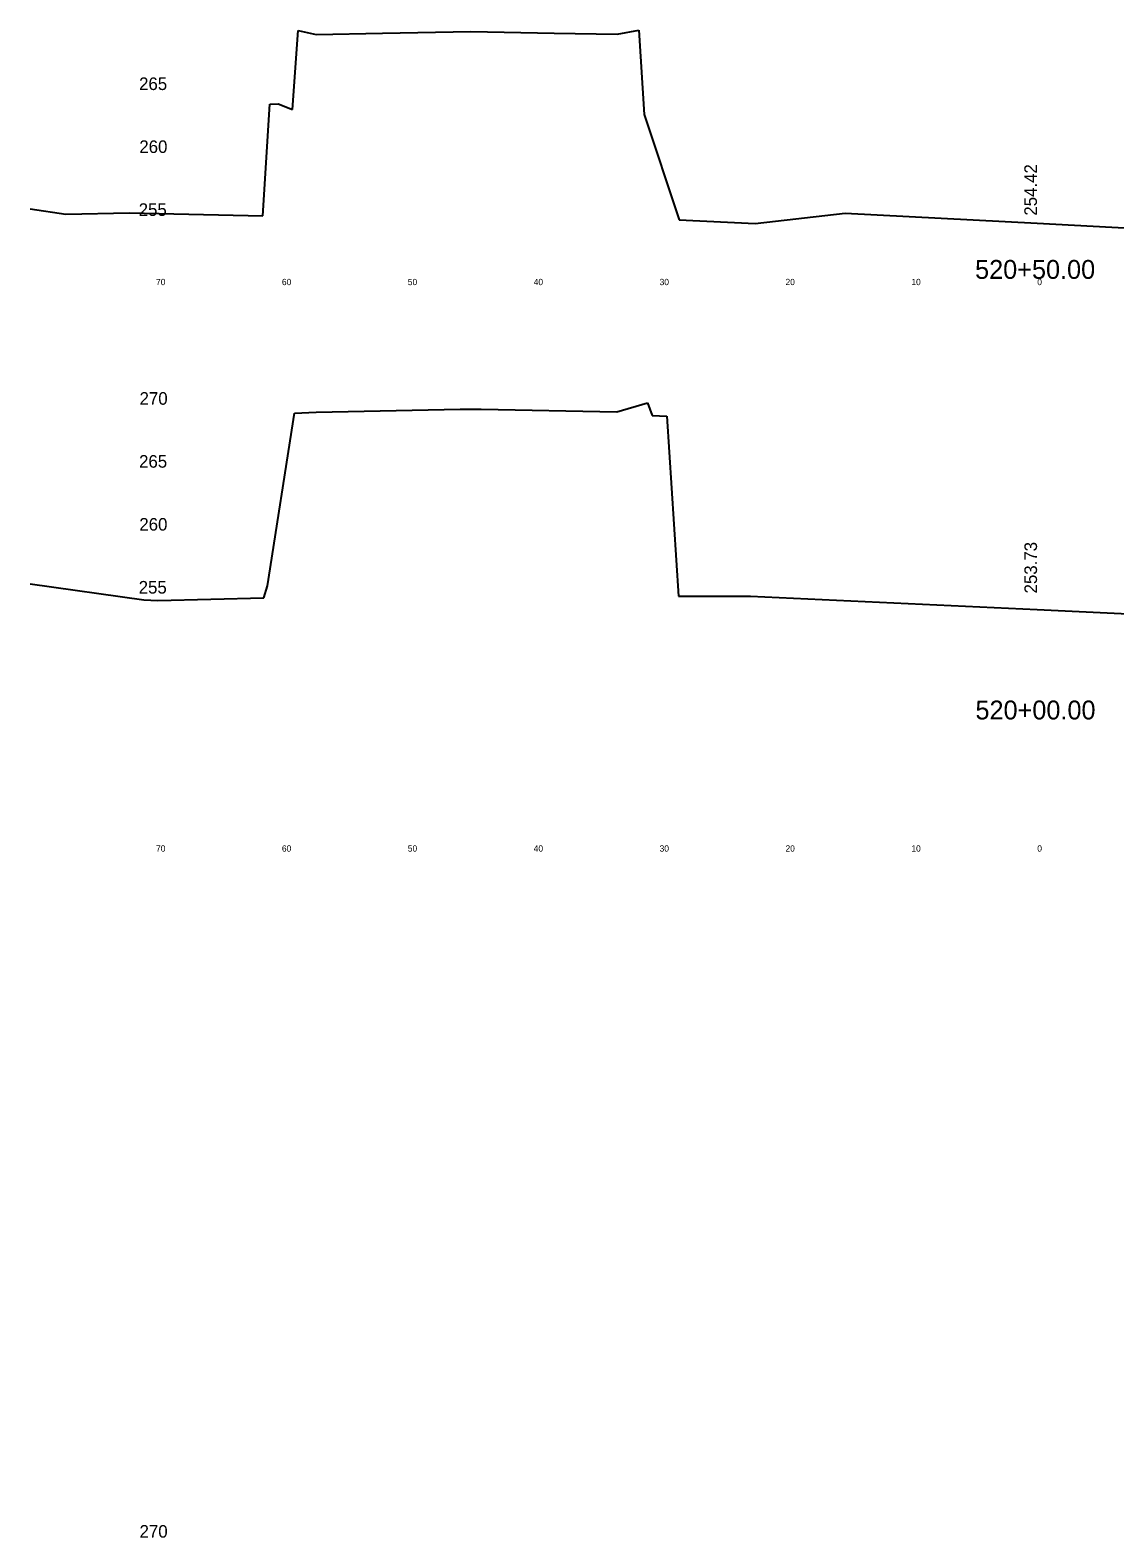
# Model space of a CAD drawing. Extents: x 1000 to 1162, y 999 to 8520.
# Drawn here: x 1000 to 1086.2, y 3820 to 3939.8 of the extents above; entities that cross this region are included whole.
import ezdxf

# ---------------------------------------------------------------- set-up
doc = ezdxf.new("R2010")
doc.units = 0
for name, color, linetype in [('Level 10', 7, 'Continuous'), ('Level 11', 7, 'Continuous'), ('Level 3', 7, 'Continuous'), ('Level 56', 7, 'Continuous'), ('Level 60', 7, 'Continuous')]:
    doc.layers.add(name, color=color, linetype=linetype)

msp = doc.modelspace()

# ---------------------------------------------------------------- linework, layer by layer
at = {"layer": 'Level 60'}
for p, q in [((1020.85, 3933.45), (1021.28, 3939.74)), ((1021.28, 3939.74), (1022.72, 3939.4)), ((1022.72, 3939.4), (1027.98, 3939.51)), ((1027.98, 3939.51), (1035.01, 3939.64)), ((1035.01, 3939.64), (1041.63, 3939.52)), ((1041.63, 3939.52), (1046.64, 3939.44)), ((1046.64, 3939.44), (1048.34, 3939.76)), ((1048.34, 3939.76), (1048.77, 3933.06)), ((1018.49, 3925.01), (1019.05, 3933.89)), ((1019.05, 3933.89), (1019.71, 3933.91)), ((1019.71, 3933.91), (1020.85, 3933.45)), ((1048.77, 3933.06), (1051.55, 3924.7)), ((1000, 3925.55), (1002.84, 3925.15)), ((1002.84, 3925.15), (1007.89, 3925.25)), ((1007.89, 3925.25), (1018.49, 3925.01)), ((1057.6, 3924.39), (1064.73, 3925.23)), ((1064.73, 3925.23), (1080, 3924.42)), ((1051.55, 3924.7), (1057.6, 3924.39)), ((1080, 3924.42), (1107.94, 3922.93)), ((1021.01, 3909.33), (1022.71, 3909.42)), ((1022.71, 3909.42), (1034.17, 3909.64)), ((1034.17, 3909.64), (1035.04, 3909.66)), ((1035.04, 3909.66), (1035.83, 3909.64)), ((1035.83, 3909.64), (1046.61, 3909.44)), ((1046.61, 3909.44), (1049.05, 3910.16)), ((1049.05, 3910.16), (1049.42, 3909.15)), ((1018.85, 3895.61), (1021.01, 3909.33)), ((1049.42, 3909.15), (1050.57, 3909.1)), ((1050.57, 3909.1), (1051.5, 3894.8)), ((1000, 3895.76), (1009.02, 3894.49)), ((1018.56, 3894.65), (1018.85, 3895.61)), ((1009.02, 3894.49), (1010.14, 3894.45)), ((1010.14, 3894.45), (1018.56, 3894.65)), ((1051.5, 3894.8), (1057.21, 3894.79)), ((1057.21, 3894.79), (1080, 3893.73)), ((1080, 3893.73), (1125.1, 3891.63))]:
    msp.add_line(p, q, dxfattribs=at)

# ---------------------------------------------------------------- texts
at = {"layer": 'Level 10'}
for s, p in [('254.42', (1079.97, 3925.02)), ('253.73', (1079.98, 3895.01))]:
    msp.add_text(s, height=1, rotation=90, dxfattribs=at).set_placement(p)
at = {"layer": 'Level 11'}
for s, p in [(' 265', (1008.28, 3935)), (' 260', (1008.3, 3930)), (' 255', (1008.25, 3925)), (' 270', (1008.32, 3910)), (' 265', (1008.28, 3905)), (' 260', (1008.3, 3900)), (' 255', (1008.25, 3895)), (' 270', (1008.32, 3820))]:
    msp.add_text(s, height=1, dxfattribs=at).set_placement(p)
at = {"layer": 'Level 3'}
for s, p in [('520+50.00', (1075.06, 3920)), ('520+00.00', (1075.09, 3885))]:
    msp.add_text(s, height=1.5, dxfattribs=at).set_placement(p)
at = {"layer": 'Level 56'}
for s, p in [('70', (1010, 3919.5)), ('60', (1020, 3919.5)), ('50', (1030, 3919.5)), ('40', (1040, 3919.5)), ('30', (1050, 3919.5)), ('20', (1060, 3919.5)), ('10', (1070, 3919.5)), ('0', (1080, 3919.5)), ('70', (1010, 3874.5)), ('60', (1020, 3874.5)), ('50', (1030, 3874.5)), ('40', (1040, 3874.5)), ('30', (1050, 3874.5)), ('20', (1060, 3874.5)), ('10', (1070, 3874.5)), ('0', (1080, 3874.5))]:
    msp.add_text(s, height=0.5, dxfattribs=at).set_placement(p)

doc.saveas('drawing.dxf')
